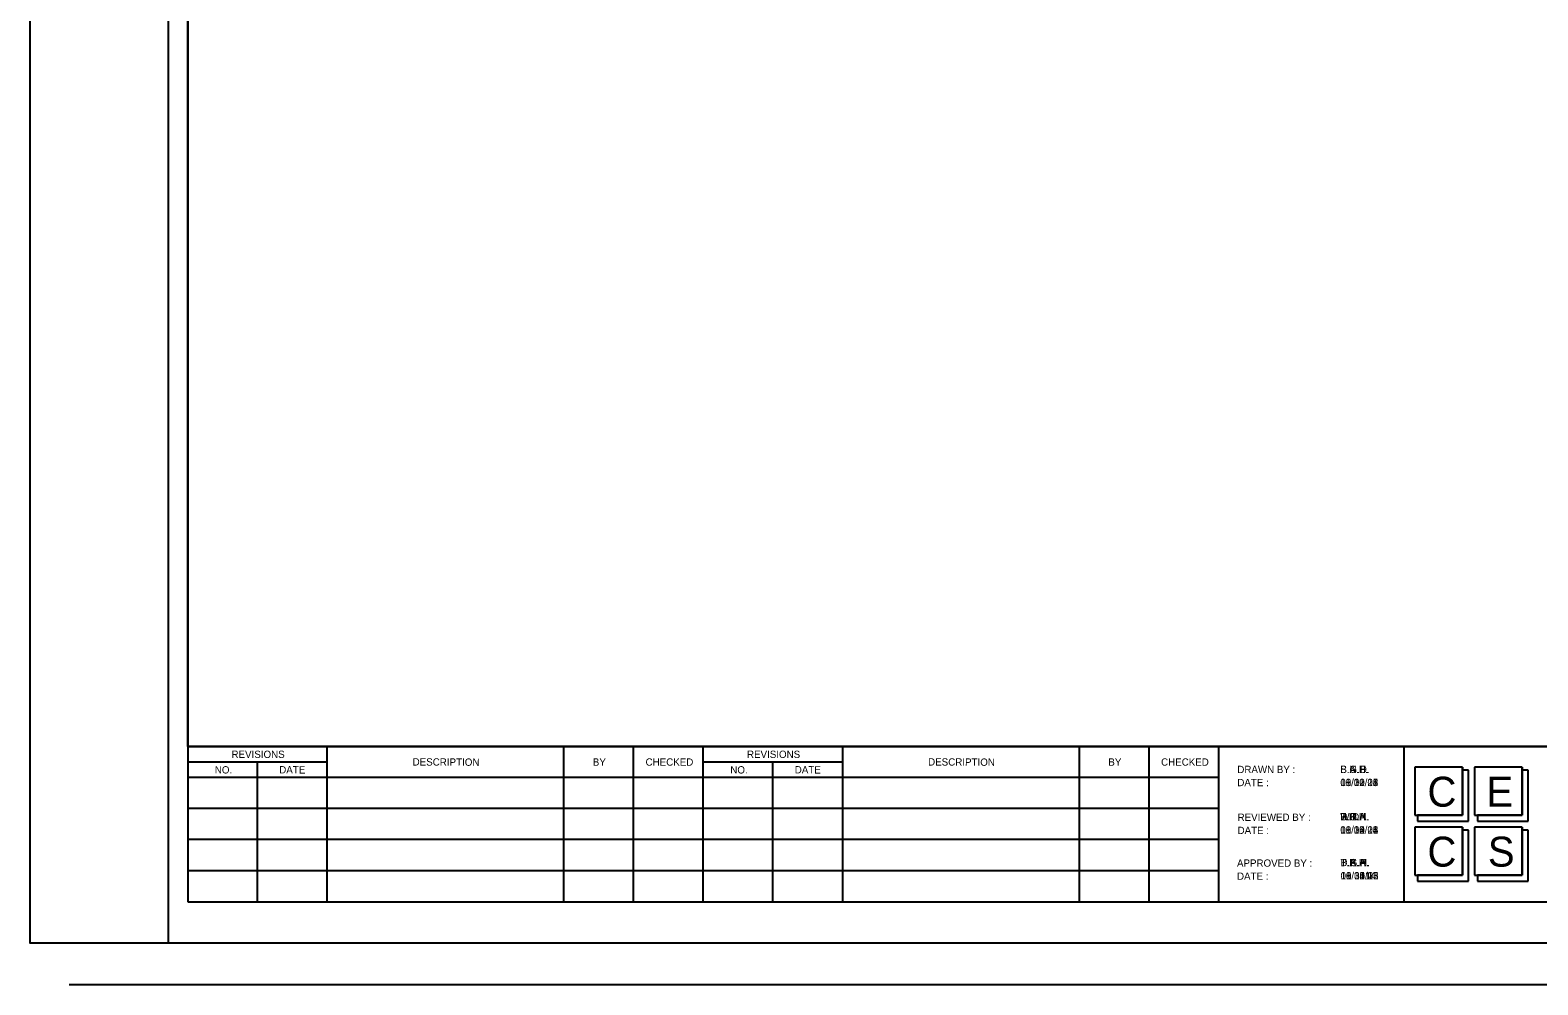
# Model space of a CAD drawing. Extents: x 309.2 to 345.2, y 57.3 to 80.3.
# Drawn here: x 309.2 to 327.37, y 57.26 to 68.76 of the extents above; entities that cross this region are included whole.
import ezdxf

# ---------------------------------------------------------------- set-up
doc = ezdxf.new("R2010")
doc.units = 0
for name, color, linetype in [('Level 2', 7, 'Continuous'), ('Plan_Clip', 7, 'Continuous'), ('RD_SHT_Bndy', 7, 'Continuous'), ('RD_SHT_IplotShp', 7, 'Continuous'), ('RD_SHT_Logo', 7, 'Continuous'), ('RD_SHT_Misc2', 7, 'Continuous'), ('RD_SHT_TX_FINAL', 7, 'Continuous'), ('RD_SHT_TX_FINAL_DR', 7, 'Continuous'), ('RD_SHT_TX_PREL', 7, 'Continuous'), ('RD_SHT_TX_PREL_DR', 7, 'Continuous'), ('RD_SHT_TX_RW', 7, 'Continuous'), ('RD_SHT_TX_RW_DR', 7, 'Continuous'), ('RD_SHT_UT_TX_FINAL', 7, 'Continuous')]:
    doc.layers.add(name, color=color, linetype=linetype)

msp = doc.modelspace()

# ---------------------------------------------------------------- linework, layer by layer
at = {"layer": 'Level 2'}
msp.add_lwpolyline([(310.865, 79.764), (344.866, 79.764), (344.866, 57.764), (310.865, 57.764)], close=True, dxfattribs=at)
at = {"layer": 'Plan_Clip'}
msp.add_lwpolyline([(311.096, 79.264), (344.596, 79.264), (344.596, 60.134), (311.096, 60.134)], close=True, dxfattribs=at)
at = {"layer": 'RD_SHT_Bndy'}
for p, q in [((311.096, 79.264), (311.096, 58.264)), ((311.096, 58.264), (344.596, 58.264)), ((344.867, 57.764), (309.667, 57.764)), ((344.866, 57.263), (309.666, 57.264))]:
    msp.add_line(p, q, dxfattribs=at)
at = {"layer": 'RD_SHT_IplotShp'}
msp.add_lwpolyline([(309.197, 79.764), (345.197, 79.764), (345.197, 57.764), (309.197, 57.764)], close=True, dxfattribs=at)
at = {"layer": 'RD_SHT_Logo'}
for p, q in [((326.457, 59.884), (325.881, 59.884)), ((325.881, 59.884), (325.881, 59.306)), ((326.457, 59.306), (326.457, 59.884)), ((326.457, 59.884), (326.457, 59.306)), ((326.529, 59.848), (326.457, 59.848)), ((326.529, 59.234), (326.529, 59.848)), ((326.601, 59.884), (326.601, 59.306)), ((327.177, 59.884), (326.601, 59.884)), ((327.177, 59.306), (327.177, 59.884)), ((327.177, 59.884), (327.177, 59.306)), ((327.249, 59.848), (327.177, 59.848)), ((327.249, 59.234), (327.249, 59.848)), ((325.881, 59.306), (326.457, 59.306)), ((326.457, 59.306), (325.917, 59.306)), ((325.917, 59.306), (325.917, 59.234)), ((325.917, 59.234), (326.529, 59.234)), ((326.601, 59.306), (327.177, 59.306)), ((327.177, 59.306), (326.637, 59.306)), ((326.637, 59.306), (326.637, 59.234)), ((326.637, 59.234), (327.249, 59.234)), ((326.457, 59.162), (325.881, 59.162)), ((325.881, 59.162), (325.881, 58.585)), ((326.457, 58.585), (326.457, 59.162)), ((326.457, 59.162), (326.457, 58.585)), ((326.529, 59.126), (326.457, 59.126)), ((326.529, 58.513), (326.529, 59.126)), ((327.177, 59.162), (326.601, 59.162)), ((326.601, 59.162), (326.601, 58.585)), ((327.177, 58.585), (327.177, 59.162)), ((327.177, 59.162), (327.177, 58.585)), ((327.249, 59.126), (327.177, 59.126)), ((327.249, 58.513), (327.249, 59.126)), ((325.881, 58.585), (326.457, 58.585)), ((326.457, 58.585), (325.917, 58.585)), ((325.917, 58.585), (325.917, 58.513)), ((325.917, 58.513), (326.529, 58.513)), ((326.601, 58.585), (327.177, 58.585)), ((327.177, 58.585), (326.637, 58.585)), ((326.637, 58.585), (326.637, 58.513)), ((326.637, 58.513), (327.249, 58.513))]:
    msp.add_line(p, q, dxfattribs=at)
at = {"layer": 'RD_SHT_Misc2'}
for p, q in [((311.096, 60.134), (344.596, 60.134)), ((312.776, 58.264), (312.776, 60.134)), ((315.628, 58.264), (315.628, 60.134)), ((316.468, 58.264), (316.468, 60.134)), ((317.308, 58.264), (317.308, 60.134)), ((318.988, 58.264), (318.988, 60.134)), ((321.84, 58.264), (321.84, 60.134)), ((322.68, 58.264), (322.68, 60.134)), ((323.52, 58.264), (323.52, 60.134)), ((325.755, 58.264), (325.755, 60.134)), ((312.776, 59.947), (311.096, 59.947)), ((311.936, 58.264), (311.936, 59.947)), ((318.988, 59.947), (317.308, 59.947)), ((318.148, 58.264), (318.148, 59.947)), ((323.52, 59.76), (311.096, 59.76)), ((323.52, 59.386), (311.096, 59.386)), ((323.52, 59.012), (311.096, 59.012)), ((323.52, 58.638), (311.096, 58.638))]:
    msp.add_line(p, q, dxfattribs=at)

# ---------------------------------------------------------------- texts
at = {"layer": 'RD_SHT_Logo'}
for s, p in [('C', (326.035, 59.409)), ('E', (326.746, 59.409)), ('C', (326.035, 58.687)), ('S', (326.763, 58.687))]:
    msp.add_text(s, height=0.361, dxfattribs=at).set_placement(p)
at = {"layer": 'RD_SHT_Misc2'}
for s, p in [('REVISIONS', (311.623, 59.996)), ('CHECKED', (316.613, 59.903)), ('REVISIONS', (317.835, 59.996)), ('CHECKED', (322.825, 59.903)), ('NO.', (311.422, 59.809)), ('NO.', (317.634, 59.809))]:
    msp.add_text(s, height=0.088, dxfattribs=at).set_placement(p)
for s, height, p in [('DESCRIPTION', 0.08817, (313.805, 59.905)), ('BY', 0.0882, (315.977, 59.903)), ('DESCRIPTION', 0.08817, (320.017, 59.905)), ('BY', 0.0882, (322.189, 59.903)), ('DATE', 0.0882, (312.198, 59.81)), ('DATE', 0.0882, (318.41, 59.81))]:
    msp.add_text(s, height=height, rotation=359.7246, dxfattribs=at).set_placement(p)
at = {"layer": 'RD_SHT_TX_FINAL'}
for s, height, p in [('DRAWN BY :', 0.0878, (323.744, 59.814)), ('DRAWN BY :', 0.0878, (323.744, 59.814)), ('B.A.H.', 0.0878, (324.985, 59.815)), ('DATE :', 0.0878, (323.744, 59.656)), ('DATE :', 0.0878, (323.744, 59.656)), ('10/31/12', 0.0878, (324.985, 59.658)), ('REVIEWED BY :', 0.08781, (323.747, 59.238)), ('REVIEWED BY :', 0.08781, (323.747, 59.238)), ('B.G.N.', 0.0878, (324.985, 59.244)), ('DATE :', 0.0878, (323.747, 59.08)), ('DATE :', 0.0878, (323.747, 59.08)), ('11/03/16', 0.0878, (324.985, 59.086)), ('APPROVED BY :', 0.08781, (323.74, 58.686)), ('APPROVED BY :', 0.08781, (323.74, 58.686)), ('B.A.H.', 0.0878, (324.988, 58.692)), ('DATE :', 0.0878, (323.74, 58.528)), ('DATE :', 0.0878, (323.74, 58.528)), ('11/10/16', 0.0878, (324.988, 58.534))]:
    msp.add_text(s, height=height, rotation=359.9996, dxfattribs=at).set_placement(p)
at = {"layer": 'RD_SHT_TX_FINAL_DR'}
for s, height, p in [('DRAWN BY :', 0.0878, (323.744, 59.814)), ('B.G.F.', 0.0878, (324.985, 59.815)), ('DATE :', 0.0878, (323.744, 59.656)), ('10/31/12', 0.0878, (324.985, 59.658)), ('REVIEWED BY :', 0.08781, (323.747, 59.238)), ('R.R.', 0.0878, (324.985, 59.244)), ('DATE :', 0.0878, (323.747, 59.08)), ('11/03/16', 0.0878, (324.985, 59.086)), ('APPROVED BY :', 0.08781, (323.74, 58.686)), ('B.G.F.', 0.0878, (324.988, 58.692)), ('DATE :', 0.0878, (323.74, 58.528)), ('11/10/16', 0.0878, (324.988, 58.534))]:
    msp.add_text(s, height=height, rotation=359.9996, dxfattribs=at).set_placement(p)
at = {"layer": 'RD_SHT_TX_PREL'}
for s, height, p in [('DRAWN BY :', 0.0878, (323.744, 59.814)), ('B.A.H.', 0.0878, (324.985, 59.815)), ('DATE :', 0.0878, (323.744, 59.656)), ('01/30/23', 0.0878, (324.985, 59.658)), ('REVIEWED BY :', 0.08781, (323.747, 59.238)), ('W.D.', 0.0878, (324.985, 59.244)), ('DATE :', 0.0878, (323.747, 59.08)), ('01/30/23', 0.0878, (324.985, 59.086)), ('APPROVED BY :', 0.08781, (323.74, 58.686)), ('B.G.N.', 0.0878, (324.988, 58.692)), ('DATE :', 0.0878, (323.74, 58.528)), ('01/31/23', 0.0878, (324.988, 58.534))]:
    msp.add_text(s, height=height, rotation=359.9996, dxfattribs=at).set_placement(p)
at = {"layer": 'RD_SHT_TX_PREL_DR'}
for s, height, p in [('DRAWN BY :', 0.0878, (323.744, 59.814)), ('DRAWN BY :', 0.0878, (323.744, 59.814)), ('B.G.F.', 0.0878, (324.985, 59.815)), ('DATE :', 0.0878, (323.744, 59.656)), ('DATE :', 0.0878, (323.744, 59.656)), ('08/12/05', 0.0878, (324.985, 59.657)), ('REVIEWED BY :', 0.08781, (323.747, 59.238)), ('REVIEWED BY :', 0.08781, (323.747, 59.238)), ('T.H.H.', 0.0878, (324.985, 59.244)), ('DATE :', 0.0878, (323.747, 59.08)), ('DATE :', 0.0878, (323.747, 59.08)), ('08/15/05', 0.0878, (324.985, 59.086)), ('APPROVED BY :', 0.08781, (323.74, 58.686)), ('APPROVED BY :', 0.08781, (323.74, 58.686)), ('T.H.H.', 0.0878, (324.988, 58.692)), ('DATE :', 0.0878, (323.74, 58.528)), ('DATE :', 0.0878, (323.74, 58.528)), ('08/15/05', 0.0878, (324.988, 58.534))]:
    msp.add_text(s, height=height, rotation=359.9996, dxfattribs=at).set_placement(p)
at = {"layer": 'RD_SHT_TX_RW'}
for s, height, p in [('DRAWN BY :', 0.0878, (323.744, 59.814)), ('B.G.D.', 0.0878, (324.985, 59.815)), ('DATE :', 0.0878, (323.744, 59.656)), ('10/12/21', 0.0878, (324.985, 59.658)), ('REVIEWED BY :', 0.08781, (323.747, 59.238)), ('B.G.N.', 0.0878, (324.985, 59.244)), ('DATE :', 0.0878, (323.747, 59.08)), ('10/12/21', 0.0878, (324.985, 59.086)), ('APPROVED BY :', 0.08781, (323.74, 58.686)), ('B.G.N.', 0.0878, (324.988, 58.692)), ('DATE :', 0.0878, (323.74, 58.528)), ('10/12/21', 0.0878, (324.988, 58.534))]:
    msp.add_text(s, height=height, rotation=359.9996, dxfattribs=at).set_placement(p)
at = {"layer": 'RD_SHT_TX_RW_DR'}
for s, height, p in [('DRAWN BY :', 0.0878, (323.744, 59.814)), ('DRAWN BY :', 0.0878, (323.744, 59.814)), ('B.G.D.', 0.0878, (324.985, 59.815)), ('DATE :', 0.0878, (323.744, 59.656)), ('DATE :', 0.0878, (323.744, 59.656)), ('10/12/21', 0.0878, (324.985, 59.658)), ('REVIEWED BY :', 0.08781, (323.747, 59.238)), ('REVIEWED BY :', 0.08781, (323.747, 59.238)), ('D.K.A.', 0.0878, (324.985, 59.244)), ('DATE :', 0.0878, (323.747, 59.08)), ('DATE :', 0.0878, (323.747, 59.08)), ('10/12/21', 0.0878, (324.985, 59.086)), ('APPROVED BY :', 0.08781, (323.74, 58.686)), ('APPROVED BY :', 0.08781, (323.74, 58.686)), ('D.K.A.', 0.0878, (324.988, 58.692)), ('DATE :', 0.0878, (323.74, 58.528)), ('DATE :', 0.0878, (323.74, 58.528)), ('10/12/21', 0.0878, (324.988, 58.534))]:
    msp.add_text(s, height=height, rotation=359.9996, dxfattribs=at).set_placement(p)
at = {"layer": 'RD_SHT_UT_TX_FINAL'}
for s, height, p in [('DRAWN BY :', 0.0878, (323.744, 59.814)), ('S.N.F.', 0.0878, (324.985, 59.815)), ('DATE :', 0.0878, (323.744, 59.656)), ('09/02/14', 0.0878, (324.985, 59.658)), ('REVIEWED BY :', 0.08781, (323.747, 59.238)), ('T.H.H.', 0.0878, (324.985, 59.244)), ('DATE :', 0.0878, (323.747, 59.08)), ('09/04/14', 0.0878, (324.985, 59.086)), ('APPROVED BY :', 0.08781, (323.74, 58.686)), ('T.H.H.', 0.0878, (324.988, 58.692)), ('DATE :', 0.0878, (323.74, 58.528)), ('09/0414', 0.0878, (324.988, 58.534))]:
    msp.add_text(s, height=height, rotation=359.9996, dxfattribs=at).set_placement(p)

doc.saveas('drawing.dxf')
